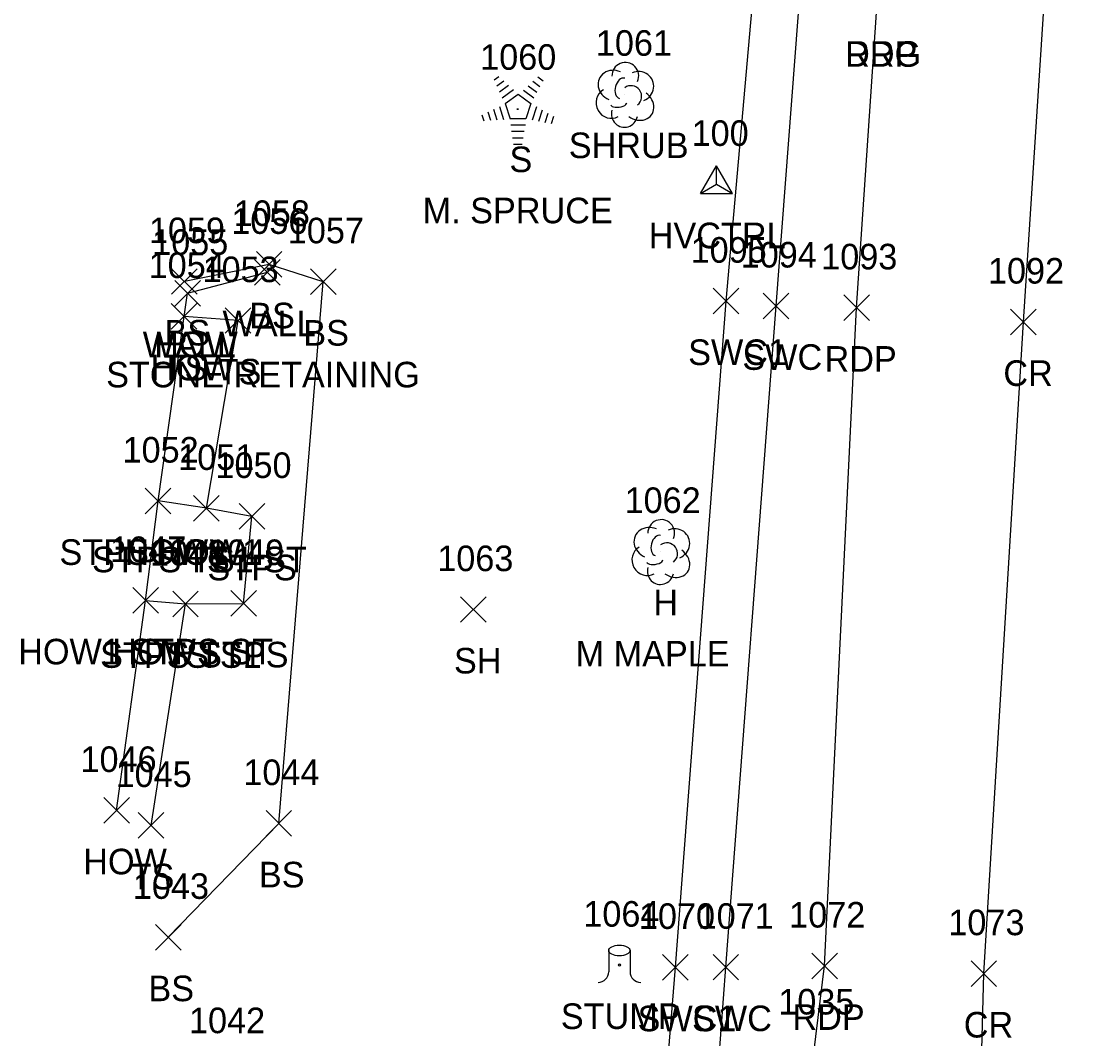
# Model space of a CAD drawing. Extents: x 1653908 to 1654393, y 539913 to 544256.
# Drawn here: x 1653941.4 to 1654023.6, y 541073 to 541152.6 of the extents above; entities that cross this region are included whole.
import ezdxf

# ---------------------------------------------------------------- set-up
doc = ezdxf.new("R2010")
doc.units = 0
for name, color, linetype in [('C_A', 7, 'Continuous'), ('C_I', 7, 'Continuous'), ('CPSM', 7, 'Continuous'), ('L_A', 7, 'Continuous'), ('L_C', 7, 'Continuous'), ('L_I', 7, 'Continuous'), ('L_TIC', 7, 'Continuous'), ('LBC', 7, 'Continuous'), ('LBF', 7, 'Continuous'), ('LELB', 7, 'Continuous'), ('LSH', 7, 'Continuous'), ('LTC', 7, 'Continuous'), ('LTD', 7, 'Continuous'), ('LTS', 7, 'Continuous'), ('LW', 7, 'Continuous'), ('P_A', 7, 'Continuous'), ('P_I', 7, 'Continuous'), ('P_TIC', 7, 'Continuous'), ('PET', 7, 'Continuous'), ('PRC', 7, 'Continuous'), ('R_A', 7, 'Continuous'), ('R_I', 7, 'Continuous'), ('R_TIC', 7, 'Continuous'), ('RSW', 7, 'Continuous')]:
    doc.layers.add(name, color=color, linetype=linetype)

msp = doc.modelspace()

# ---------------------------------------------------------------- linework, layer by layer
at = {"layer": 'CPSM'}
for p, q in [((1653994.551, 541139.075), (1653995.801, 541141.24)), ((1653997.051, 541139.075), (1653995.801, 541141.24)), ((1653995.801, 541139.796), (1653995.801, 541141.24)), ((1653994.551, 541139.075), (1653995.801, 541139.796)), ((1653995.801, 541139.796), (1653995.801, 541139.796)), ((1653995.801, 541139.796), (1653997.051, 541139.075)), ((1653994.551, 541139.075), (1653997.051, 541139.075))]:
    msp.add_line(p, q, dxfattribs=at)
at = {"layer": 'L_TIC'}
for points in [[(1653959.691, 541131.919), (1653961.691, 541133.919)], [(1653961.691, 541131.919), (1653959.691, 541133.919)], [(1653959.828, 541132.538), (1653961.828, 541134.538)], [(1653961.828, 541132.538), (1653959.828, 541134.538)], [(1653953.206, 541131.194), (1653955.206, 541133.194)], [(1653955.206, 541131.194), (1653953.206, 541133.194)], [(1653964.055, 541131.183), (1653966.055, 541133.183)], [(1653966.055, 541131.183), (1653964.055, 541133.183)], [(1653953.454, 541130.278), (1653955.454, 541132.278)], [(1653955.454, 541130.278), (1653953.454, 541132.278)], [(1653953.454, 541130.278), (1653955.454, 541132.278)], [(1653955.454, 541130.278), (1653953.454, 541132.278)], [(1653953.178, 541128.469), (1653955.178, 541130.469)], [(1653955.178, 541128.469), (1653953.178, 541130.469)], [(1653953.178, 541128.469), (1653955.178, 541130.469)], [(1653955.178, 541128.469), (1653953.178, 541130.469)], [(1653957.392, 541128.147), (1653959.392, 541130.147)], [(1653959.392, 541128.147), (1653957.392, 541130.147)], [(1653951.139, 541114.04), (1653953.139, 541116.04)], [(1653953.139, 541114.04), (1653951.139, 541116.04)], [(1653951.139, 541114.04), (1653953.139, 541116.04)], [(1653953.139, 541114.04), (1653951.139, 541116.04)], [(1653954.921, 541113.464), (1653956.921, 541115.464)], [(1653956.921, 541113.464), (1653954.921, 541115.464)], [(1653954.921, 541113.464), (1653956.921, 541115.464)], [(1653956.921, 541113.464), (1653954.921, 541115.464)], [(1653958.485, 541112.835), (1653960.485, 541114.835)], [(1653960.485, 541112.835), (1653958.485, 541114.835)], [(1653950.173, 541106.262), (1653952.173, 541108.262)], [(1653952.173, 541106.262), (1653950.173, 541108.262)], [(1653950.173, 541106.262), (1653952.173, 541108.262)], [(1653952.173, 541106.262), (1653950.173, 541108.262)], [(1653953.289, 541105.993), (1653955.289, 541107.993)], [(1653955.289, 541105.993), (1653953.289, 541107.993)], [(1653953.289, 541105.993), (1653955.289, 541107.993)], [(1653955.289, 541105.993), (1653953.289, 541107.993)], [(1653957.833, 541106.027), (1653959.833, 541108.027)], [(1653959.833, 541106.027), (1653957.833, 541108.027)], [(1653975.782, 541105.552), (1653977.782, 541107.552)], [(1653977.782, 541105.552), (1653975.782, 541107.552)], [(1653947.907, 541089.85), (1653949.907, 541091.85)], [(1653949.907, 541089.85), (1653947.907, 541091.85)], [(1653950.593, 541088.676), (1653952.593, 541090.676)], [(1653952.593, 541088.676), (1653950.593, 541090.676)], [(1653960.581, 541088.828), (1653962.581, 541090.828)], [(1653962.581, 541088.828), (1653960.581, 541090.828)], [(1653951.946, 541079.931), (1653953.946, 541081.931)], [(1653953.946, 541079.931), (1653951.946, 541081.931)]]:
    msp.add_lwpolyline(points, dxfattribs=at)
at = {"layer": 'LBC'}
msp.add_lwpolyline([(1653948.907, 541090.85), (1653951.173, 541107.262), (1653952.139, 541115.04), (1653954.178, 541129.469), (1653954.454, 541131.278)], dxfattribs=at)
at = {"layer": 'LBF'}
msp.add_lwpolyline([(1653951.173, 541107.262), (1653954.289, 541106.993), (1653958.833, 541107.027), (1653959.485, 541113.835), (1653955.921, 541114.464), (1653952.139, 541115.04)], dxfattribs=at)
at = {"layer": 'LELB'}
for points in [[(1653952.946, 541080.931), (1653961.581, 541089.828), (1653965.055, 541132.183), (1653960.828, 541133.538), (1653954.206, 541132.194)], [(1653955.921, 541114.464), (1653958.392, 541129.147), (1653954.178, 541129.469)], [(1653951.593, 541089.676), (1653954.289, 541106.993)]]:
    msp.add_lwpolyline(points, dxfattribs=at)
at = {"layer": 'LSH'}
msp.add_line((1653988.613, 541146.843), (1653988.613, 541146.843), dxfattribs=at)
msp.add_line((1653988.613, 541146.843), (1653988.613, 541146.843), dxfattribs=at)
msp.add_arc((1653988.66, 541148.277), 1.047, 335.52715, 180.95627, dxfattribs=at)
for centre, major_axis, ratio, start_param, end_param in [((1653987.822, 541147.51), (1.21, -0.512), 0.895232, 1.570796, 4.712389), ((1653989.655, 541147.427), (-1.141, -0.483), 0.949671, 1.570796, 4.712389), ((1653988.405, 541147.302), (-0.208, -0.792), 0.645439, 3.141593, 6.283185), ((1653987.53, 541146.135), (0.584, -1.042), 0.959034, 3.141593, 6.283185), ((1653989.113, 541146.677), (-0.5, 0.667), 0.989748, 3.141593, 6.283185), ((1653989.613, 541146.01), (-1.09, 0.792), 0.841452, 1.570796, 4.712389), ((1653988.614, 541145.343), (0.265, 1.061), 0.942809, 1.570796, 4.712389), ((1653988.155, 541146.093), (-0.625, -0.083), 0.423636, 0, 3.141593)]:
    msp.add_ellipse(centre, major_axis=major_axis, ratio=ratio, start_param=start_param, end_param=end_param, dxfattribs=at)
at = {"layer": 'LTC'}
for p, q in [((1653978.417, 541147.956), (1653978.772, 541148.214)), ((1653978.627, 541147.491), (1653979.156, 541147.875)), ((1653981.444, 541147.848), (1653981.994, 541147.449)), ((1653981.816, 541148.197), (1653982.235, 541147.892)), ((1653978.836, 541147.025), (1653979.54, 541147.536)), ((1653979.046, 541146.559), (1653979.924, 541147.197)), ((1653980.702, 541147.152), (1653981.512, 541146.563)), ((1653981.074, 541147.5), (1653981.753, 541147.006)), ((1653979.271, 541146.104), (1653980.282, 541146.839)), ((1653980.282, 541146.839), (1653981.279, 541146.114)), ((1653977.905, 541145.452), (1653978.117, 541144.801)), ((1653978.361, 541145.669), (1653978.632, 541144.833)), ((1653978.816, 541145.885), (1653979.147, 541144.866)), ((1653979.271, 541146.104), (1653979.658, 541144.911)), ((1653981.279, 541146.114), (1653980.888, 541144.911)), ((1653981.717, 541145.843), (1653981.379, 541144.803)), ((1653982.161, 541145.593), (1653981.874, 541144.708)), ((1653977.45, 541145.236), (1653977.602, 541144.768)), ((1653980.888, 541144.911), (1653979.658, 541144.911)), ((1653982.606, 541145.343), (1653982.369, 541144.613)), ((1653983.05, 541145.092), (1653982.864, 541144.518)), ((1653980.85, 541144.411), (1653979.705, 541144.411)), ((1653980.766, 541143.911), (1653979.778, 541143.911)), ((1653980.682, 541143.411), (1653979.851, 541143.411)), ((1653980.599, 541142.911), (1653979.924, 541142.911))]:
    msp.add_line(p, q, dxfattribs=at)
at = {"layer": 'LTD'}
msp.add_line((1653991.422, 541111.099), (1653991.422, 541111.099), dxfattribs=at)
msp.add_line((1653991.422, 541111.099), (1653991.422, 541111.099), dxfattribs=at)
msp.add_arc((1653991.469, 541112.533), 1.047, 335.52715, 180.95627, dxfattribs=at)
for centre, major_axis, ratio, start_param, end_param in [((1653990.63, 541111.766), (1.21, -0.512), 0.895232, 1.570796, 4.712389), ((1653992.464, 541111.683), (-1.141, -0.483), 0.949671, 1.570796, 4.712389), ((1653991.214, 541111.558), (-0.208, -0.792), 0.645439, 3.141593, 6.283185), ((1653991.922, 541110.933), (-0.5, 0.667), 0.989748, 3.141593, 6.283185), ((1653990.339, 541110.391), (0.584, -1.042), 0.959034, 3.141593, 6.283185), ((1653992.422, 541110.266), (-1.09, 0.792), 0.841452, 1.570796, 4.712389), ((1653990.964, 541110.349), (-0.625, -0.083), 0.423636, 0, 3.141593), ((1653991.423, 541109.599), (0.265, 1.061), 0.942809, 1.570796, 4.712389)]:
    msp.add_ellipse(centre, major_axis=major_axis, ratio=ratio, start_param=start_param, end_param=end_param, dxfattribs=at)
at = {"layer": 'LTS'}
for p, q in [((1653987.369, 541079.898), (1653987.369, 541078.231)), ((1653989.035, 541079.731), (1653989.035, 541079.898)), ((1653989.035, 541079.898), (1653989.035, 541078.231)), ((1653988.202, 541078.756), (1653988.202, 541078.756)), ((1653988.202, 541078.756), (1653988.202, 541078.756)), ((1653988.202, 541078.731), (1653988.202, 541078.731))]:
    msp.add_line(p, q, dxfattribs=at)
msp.add_circle((1653988.202, 541078.756), 0.0833, dxfattribs=at)
for centre, start, end in [((1653986.535, 541078.231), 270, 360), ((1653989.869, 541078.231), 180, 270)]:
    msp.add_arc(centre, 0.833, start, end, dxfattribs=at)
msp.add_ellipse((1653988.202, 541079.898), major_axis=(-0.833, 0), ratio=0.5, dxfattribs=at)
at = {"layer": 'LW'}
msp.add_lwpolyline([(1653954.454, 541131.278), (1653960.691, 541132.919)], dxfattribs=at)
at = {"layer": 'P_TIC'}
for points in [[(1654005.743, 541129.143), (1654007.743, 541131.143)], [(1654007.743, 541129.143), (1654005.743, 541131.143)], [(1654018.776, 541128.034), (1654020.776, 541130.034)], [(1654020.776, 541128.034), (1654018.776, 541130.034)], [(1654003.237, 541077.688), (1654005.237, 541079.688)], [(1654005.237, 541077.688), (1654003.237, 541079.688)], [(1654015.681, 541077.091), (1654017.681, 541079.091)], [(1654017.681, 541077.091), (1654015.681, 541079.091)]]:
    msp.add_lwpolyline(points, dxfattribs=at)
at = {"layer": 'PET'}
msp.add_lwpolyline([(1654002.711, 541022.85), (1654002.8, 541044.575), (1654003.387, 541071.89), (1654004.237, 541078.688), (1654006.743, 541130.143), (1654008.352, 541153.982), (1654010.069, 541183.44), (1654012.885, 541209.942), (1654016.448, 541249.52), (1654022.907, 541308.117), (1654024.639, 541328.517), (1654031.788, 541410.001), (1654035.81, 541442.822), (1654037.011, 541460.368), (1654040.035, 541491.488), (1654045.583, 541525.885), (1654049.594, 541568.112), (1654053.328, 541590.161), (1654054.271, 541598.349), (1654062.589, 541587.523), (1654071.875, 541577.056), (1654070.193, 541559.907), (1654067.659, 541531.505), (1654064.32, 541497.282)], dxfattribs=at)
at = {"layer": 'PRC'}
msp.add_lwpolyline([(1654015.219, 541022.422), (1654016.681, 541078.091), (1654019.776, 541129.034), (1654023.084, 541180.037), (1654025.544, 541208.787), (1654028.973, 541248.663), (1654033.814, 541299.535), (1654044.549, 541409.641), (1654048.398, 541449.608), (1654049.075, 541458.744), (1654052.537, 541493.395), (1654055.938, 541523.167), (1654060.179, 541564.47), (1654062.589, 541587.523)], dxfattribs=at)
at = {"layer": 'R_TIC'}
for points in [[(1653995.533, 541129.668), (1653997.533, 541131.668)], [(1653997.533, 541129.668), (1653995.533, 541131.668)], [(1653999.449, 541129.29), (1654001.449, 541131.29)], [(1654001.449, 541129.29), (1653999.449, 541131.29)], [(1653991.581, 541077.58), (1653993.581, 541079.58)], [(1653993.581, 541077.58), (1653991.581, 541079.58)], [(1653995.516, 541077.59), (1653997.516, 541079.59)], [(1653997.516, 541077.59), (1653995.516, 541079.59)]]:
    msp.add_lwpolyline(points, dxfattribs=at)
at = {"layer": 'RSW'}
for points in [[(1653995.608, 541066.356), (1653991.562, 541066.058), (1653992.581, 541078.58), (1653996.533, 541130.668), (1653999, 541158.35), (1654000.182, 541180.988), (1654002.98, 541210.258), (1654005.98, 541249.997), (1654010.225, 541310.577)], [(1653995.608, 541066.356), (1653996.516, 541078.59), (1654000.449, 541130.29), (1654004.364, 541181.55), (1654006.659, 541209.967), (1654009.695, 541249.872), (1654014.15, 541310.291), (1654010.225, 541310.577)]]:
    msp.add_lwpolyline(points, dxfattribs=at)

# ---------------------------------------------------------------- texts
at = {"layer": 'C_A'}
msp.add_text('HVCTRL', height=2, dxfattribs=at).set_placement((1653990.494, 541134.796))
at = {"layer": 'C_I'}
msp.add_text('100', height=2, dxfattribs=at).set_placement((1653993.841, 541142.796))
at = {"layer": 'L_A'}
for s, p in [('SHRUB', (1653984.243, 541141.843)), ('S', (1653979.608, 541140.748)), ('WALL', (1653957.18, 541127.919)), ('BS', (1653959.269, 541128.538)), ('BS', (1653952.647, 541127.194)), ('BS', (1653963.496, 541127.183)), ('WALL', (1653950.943, 541126.278)), ('HOW', (1653951.84, 541126.278)), ('HOW', (1653951.564, 541124.469)), ('TS', (1653952.588, 541124.469)), ('TS', (1653956.801, 541124.147)), ('STPS HOW1', (1653944.439, 541110.04)), ('HOW', (1653949.525, 541110.04)), ('STPS TS1 ST', (1653946.984, 541109.464)), ('TS', (1653954.33, 541109.464)), ('STPS', (1653956.005, 541108.835)), ('H', (1653990.855, 541106.099)), ('HOW1 STPS ST', (1653941.213, 541102.262)), ('STPS TS1', (1653947.612, 541101.993)), ('HOW', (1653948.559, 541102.262)), ('TS', (1653952.699, 541101.993)), ('STPS', (1653955.353, 541102.027)), ('SH', (1653975.27, 541101.552)), ('HOW', (1653946.293, 541085.85)), ('TS', (1653950.003, 541084.676)), ('BS', (1653960.022, 541084.828)), ('BS', (1653951.387, 541075.931)), ('STUMP', (1653983.623, 541073.758))]:
    msp.add_text(s, height=2, dxfattribs=at).set_placement(p)
at = {"layer": 'L_C'}
for s, p in [('M. SPRUCE', (1653972.821, 541136.748)), ('STONE RETAINING', (1653948.086, 541123.919)), ('M MAPLE', (1653984.777, 541102.099))]:
    msp.add_text(s, height=2, dxfattribs=at).set_placement(p)
at = {"layer": 'L_I'}
for s, p in [('1061', (1653986.361, 541149.843)), ('1060', (1653977.317, 541148.748)), ('1058', (1653958.057, 541136.538)), ('1059', (1653951.427, 541135.194)), ('1056', (1653957.865, 541135.919)), ('1057', (1653962.283, 541135.183)), ('1055', (1653951.683, 541134.278)), ('1055', (1653951.683, 541134.278)), ('1054', (1653951.407, 541132.469)), ('1054', (1653951.407, 541132.469)), ('1053', (1653955.62, 541132.147)), ('1052', (1653949.368, 541118.04)), ('1052', (1653949.368, 541118.04)), ('1051', (1653953.716, 541117.464)), ('1051', (1653953.716, 541117.464)), ('1050', (1653956.627, 541116.835)), ('1062', (1653988.604, 541114.099)), ('1047', (1653948.402, 541110.262)), ('1047', (1653948.402, 541110.262)), ('1048', (1653951.518, 541109.993)), ('1048', (1653951.518, 541109.993)), ('1049', (1653956.054, 541110.027)), ('1063', (1653973.963, 541109.552)), ('1046', (1653946.081, 541093.85)), ('1045', (1653948.822, 541092.676)), ('1044', (1653958.81, 541092.828)), ('1043', (1653950.175, 541083.931)), ('1064', (1653985.379, 541081.758)), ('1042', (1653954.561, 541073.43))]:
    msp.add_text(s, height=2, dxfattribs=at).set_placement(p)
at = {"layer": 'LTC'}
msp.add_text('.', height=1.037, rotation=270, dxfattribs=at).set_placement((1653980.165, 541145.852))
at = {"layer": 'P_A'}
for s, p in [('RDP', (1654005.841, 541148.982)), ('RDP', (1654004.231, 541125.143)), ('CR', (1654018.209, 541124.034)), ('RDP', (1654001.725, 541073.688)), ('CR', (1654015.114, 541073.091))]:
    msp.add_text(s, height=2, dxfattribs=at).set_placement(p)
at = {"layer": 'P_I'}
for s, p in [('1093', (1654003.972, 541133.143)), ('1092', (1654017.005, 541132.034)), ('1072', (1654001.466, 541081.688)), ('1073', (1654013.909, 541081.091)), ('1035', (1654000.615, 541074.89)), ('1035', (1654000.615, 541074.89))]:
    msp.add_text(s, height=2, dxfattribs=at).set_placement(p)
at = {"layer": 'R_A'}
for s, p in [('DRG', (1654005.841, 541148.982)), ('SWC1', (1653993.573, 541125.668)), ('SWC', (1653997.811, 541125.29)), ('SWC1', (1653989.621, 541073.58)), ('SWC', (1653993.878, 541073.59))]:
    msp.add_text(s, height=2, dxfattribs=at).set_placement(p)
at = {"layer": 'R_I'}
for s, p in [('1095', (1653993.762, 541133.668)), ('1094', (1653997.677, 541133.29)), ('1070', (1653989.723, 541081.58)), ('1071', (1653994.312, 541081.59))]:
    msp.add_text(s, height=2, dxfattribs=at).set_placement(p)

doc.saveas('drawing.dxf')
